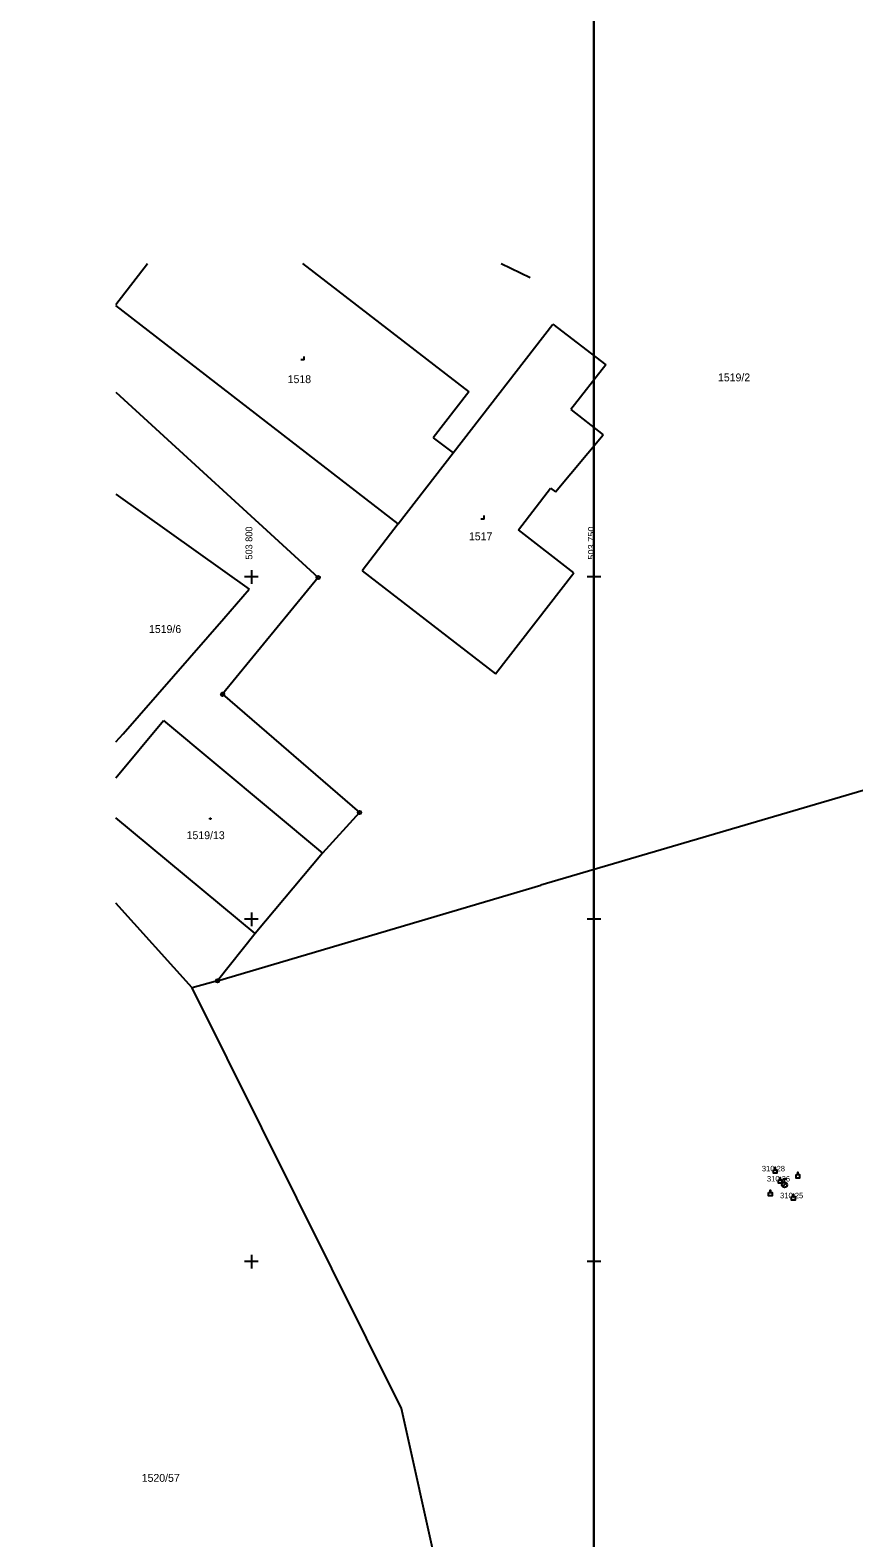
# Model space of a CAD drawing. Extents: x -504375 to -503125, y -1118000 to -1116474.
# Drawn here: x -503832.3 to -503712, y -1116940.3 to -1116720.2 of the extents above; entities that cross this region are included whole.
import ezdxf

# ---------------------------------------------------------------- set-up
doc = ezdxf.new("R2010")
doc.units = 0
for name, color, linetype in [('Podkladové mapy', 7, 'Continuous'), ('Síť dekadická', 7, 'Continuous'), ('Vodovod', 7, 'Continuous'), ('Vrstva 34', 7, 'Continuous'), ('Výšky bodů plotr', 7, 'Continuous')]:
    doc.layers.add(name, color=color, linetype=linetype)

msp = doc.modelspace()

# ---------------------------------------------------------------- linework, layer by layer
at = {"layer": 'Podkladové mapy'}
for p, q in [((-503819.807, -1116760.226), (-503815.169, -1116754.229)), ((-503792.539, -1116754.227), (-503768.27, -1116772.99)), ((-503763.514, -1116754.226), (-503759.29, -1116756.3)), ((-503778.57, -1116792.27), (-503819.807, -1116760.376)), ((-503770.55, -1116781.9), (-503756.01, -1116763.08)), ((-503756.01, -1116763.08), (-503748.24, -1116769.04)), ((-503792.3, -1116768.33), (-503792.8, -1116768.33)), ((-503792.3, -1116768.33), (-503792.3, -1116767.83)), ((-503748.24, -1116769.04), (-503753.35, -1116775.55)), ((-503819.807, -1116773.033), (-503790.25, -1116800.1)), ((-503768.27, -1116772.99), (-503773.44, -1116779.68)), ((-503753.35, -1116775.55), (-503748.63, -1116779.28)), ((-503773.44, -1116779.68), (-503770.55, -1116781.9)), ((-503755.62, -1116787.59), (-503748.63, -1116779.28)), ((-503778.57, -1116792.27), (-503770.55, -1116781.9)), ((-503761.02, -1116793.11), (-503756.33, -1116787.04)), ((-503756.33, -1116787.04), (-503755.62, -1116787.59)), ((-503819.807, -1116787.945), (-503800.35, -1116801.78)), ((-503766.02, -1116791.56), (-503766.52, -1116791.56)), ((-503766.02, -1116791.56), (-503766.02, -1116791.06)), ((-503778.57, -1116792.27), (-503783.85, -1116799.1)), ((-503752.9, -1116799.39), (-503761.02, -1116793.11)), ((-503790.25, -1116800.1), (-503804.21, -1116817.15)), ((-503783.85, -1116799.1), (-503764.34, -1116814.18)), ((-503764.34, -1116814.18), (-503752.9, -1116799.39)), ((-503804.03, -1116806.06), (-503800.35, -1116801.78)), ((-503818.74, -1116822.93), (-503804.03, -1116806.06)), ((-503804.21, -1116817.15), (-503784.22, -1116834.41)), ((-503819.807, -1116829.327), (-503812.86, -1116820.96)), ((-503812.86, -1116820.96), (-503789.6, -1116840.37)), ((-503819.807, -1116824.104), (-503818.74, -1116822.93)), ((-503704.16, -1116829.27), (-503757.75, -1116845)), ((-503799.46, -1116852.08), (-503819.807, -1116835.193)), ((-503806.07, -1116835.22), (-503805.92, -1116835.22)), ((-503806.07, -1116835.37), (-503806.07, -1116835.22)), ((-503805.92, -1116835.37), (-503806.07, -1116835.37)), ((-503805.92, -1116835.22), (-503805.92, -1116835.37)), ((-503784.22, -1116834.41), (-503789.6, -1116840.37)), ((-503789.6, -1116840.37), (-503799.46, -1116852.08)), ((-503804.95, -1116858.99), (-503757.75, -1116845)), ((-503808.65, -1116860), (-503819.807, -1116847.637)), ((-503799.46, -1116852.08), (-503804.95, -1116858.99)), ((-503804.95, -1116858.99), (-503808.65, -1116860)), ((-503778.07, -1116921.42), (-503808.65, -1116860)), ((-503763.19, -1116988.95), (-503778.07, -1116921.42))]:
    msp.add_line(p, q, dxfattribs=at)
for centre, radius in [((-503790.25, -1116800.1), 0.25), ((-503790.25, -1116800.1), 0.005), ((-503804.21, -1116817.15), 0.25), ((-503804.21, -1116817.15), 0.005), ((-503784.22, -1116834.41), 0.25), ((-503784.22, -1116834.41), 0.005), ((-503804.95, -1116858.99), 0.25), ((-503804.95, -1116858.99), 0.005)]:
    msp.add_circle(centre, radius, dxfattribs=at)
at = {"layer": 'Síť dekadická'}
for points in [[(-503750, -1116500), (-503750, -1117000), (-504375, -1117000), (-504375, -1116500)], [(-503125, -1116500), (-503125, -1117000), (-503750, -1117000), (-503750, -1116500)]]:
    msp.add_lwpolyline(points, close=True, dxfattribs=at)
at = {"layer": 'Vodovod'}
for p, q in [((-503722.454, -1116889.021), (-503721.864, -1116888.558)), ((-503722.41, -1116887.915), (-503721.91, -1116887.915)), ((-503722.16, -1116888.415), (-503722.16, -1116887.915))]:
    msp.add_line(p, q, dxfattribs=at)
for points in [[(-503723.469, -1116886.576), (-503723.469, -1116886.261), (-503723.595, -1116886.261), (-503723.595, -1116886.576)], [(-503722.729, -1116888.056), (-503722.729, -1116887.741), (-503722.855, -1116887.741), (-503722.855, -1116888.056)], [(-503720.149, -1116887.286), (-503720.149, -1116886.971), (-503720.275, -1116886.971), (-503720.275, -1116887.286)], [(-503724.169, -1116889.906), (-503724.169, -1116889.591), (-503724.295, -1116889.591), (-503724.295, -1116889.906)], [(-503720.809, -1116890.506), (-503720.809, -1116890.191), (-503720.935, -1116890.191), (-503720.935, -1116890.506)]]:
    msp.add_lwpolyline(points, dxfattribs=at)
for points in [[(-503723.784, -1116886.576), (-503723.28, -1116886.576), (-503723.28, -1116887.08), (-503723.784, -1116887.08)], [(-503723.044, -1116888.056), (-503722.54, -1116888.056), (-503722.54, -1116888.56), (-503723.044, -1116888.56)], [(-503720.464, -1116887.286), (-503719.96, -1116887.286), (-503719.96, -1116887.79), (-503720.464, -1116887.79)], [(-503724.484, -1116889.906), (-503723.98, -1116889.906), (-503723.98, -1116890.41), (-503724.484, -1116890.41)], [(-503721.124, -1116890.506), (-503720.62, -1116890.506), (-503720.62, -1116891.01), (-503721.124, -1116891.01)]]:
    msp.add_lwpolyline(points, close=True, dxfattribs=at)
msp.add_circle((-503722.16, -1116888.79), 0.375, dxfattribs=at)
at = {"layer": 'Vrstva 34'}
for p, q in [((-503799, -1116800), (-503801, -1116800)), ((-503800, -1116799), (-503800, -1116801)), ((-503749, -1116800), (-503751, -1116800)), ((-503750, -1116799), (-503750, -1116801)), ((-503800, -1116849), (-503800, -1116851)), ((-503750, -1116849), (-503750, -1116851)), ((-503799, -1116850), (-503801, -1116850)), ((-503749, -1116850), (-503751, -1116850)), ((-503800, -1116899), (-503800, -1116901)), ((-503750, -1116899), (-503750, -1116901)), ((-503799, -1116900), (-503801, -1116900)), ((-503749, -1116900), (-503751, -1116900))]:
    msp.add_line(p, q, dxfattribs=at)
msp.add_lwpolyline([(-503750, -1116754.229), (-503750, -1117230.829)], dxfattribs=at)

# ---------------------------------------------------------------- texts
at = {"layer": 'Podkladové mapy'}
for s, p in [('1518', (-503794.71, -1116771.71)), ('1519/2', (-503731.88, -1116771.45)), ('1517', (-503768.24, -1116794.66)), ('1519/6', (-503814.957, -1116808.2)), ('1519/13', (-503809.46, -1116838.3)), ('1520/57', (-503816.02, -1116932.15))]:
    msp.add_text(s, height=1.15, dxfattribs=at).set_placement(p)
at = {"layer": 'Vrstva 34'}
for s, p in [('503 800', (-503799.863, -1116797.481)), ('503 750', (-503749.863, -1116797.481))]:
    msp.add_text(s, height=1, rotation=90, dxfattribs=at).set_placement(p)
at = {"layer": 'Výšky bodů plotr'}
for s, p in [('310.28 ', (-503725.47, -1116886.81)), ('310.26 ', (-503724.73, -1116888.29)), ('310.25 ', (-503722.81, -1116890.74))]:
    msp.add_text(s, height=0.8, dxfattribs=at).set_placement(p)

doc.saveas('drawing.dxf')
